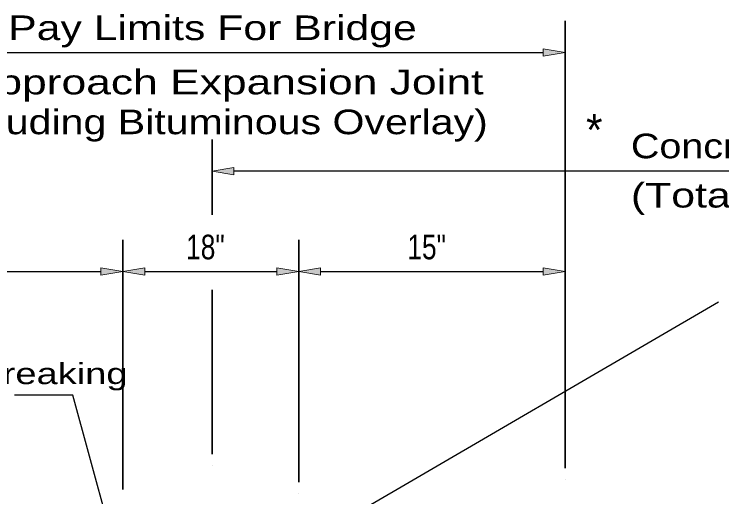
# Model space of a CAD drawing. Extents: x 36.4 to 71.7, y 0.5 to 22.5.
# Drawn here: x 46.897 to 50.926, y 10.127 to 12.873 of the extents above; entities that cross this region are included whole.
import ezdxf

# ---------------------------------------------------------------- set-up
doc = ezdxf.new("R2010")
doc.units = 0
doc.header["$LTSCALE"] = 0.056
for name, color, linetype, lineweight in [('1', 7, 'Continuous', 40), ('3', 7, 'Continuous', 13), ('6', 7, 'Continuous', 13)]:
    doc.layers.add(name, color=color, linetype=linetype, lineweight=lineweight)

msp = doc.modelspace()

# ---------------------------------------------------------------- hatches: boundary and pattern name
at = {"layer": '1'}
for points in [[(49.90942, 12.63425), (49.90942, 12.67592), (50.03442, 12.65508), (50.03442, 12.65508)], [(48.14858, 11.95783), (48.14858, 11.9995), (48.02358, 11.97867), (48.02358, 11.97867)], [(47.39025, 11.38717), (47.39025, 11.42883), (47.51525, 11.408), (47.51525, 11.408)], [(47.64025, 11.38717), (47.64025, 11.42883), (47.51525, 11.408), (47.51525, 11.408)], [(48.39192, 11.38717), (48.39192, 11.42883), (48.51692, 11.408), (48.51692, 11.408)], [(48.64192, 11.38717), (48.64192, 11.42883), (48.51692, 11.408), (48.51692, 11.408)], [(49.90942, 11.38717), (49.90942, 11.42883), (50.03442, 11.408), (50.03442, 11.408)]]:
    msp.add_hatch(color=256, dxfattribs=at).paths.add_polyline_path(points)

# ---------------------------------------------------------------- linework, layer by layer
at = {"layer": '1', "lineweight": 35}
for p, q in [((50.03442, 10.35225), (50.03442, 12.83508)), ((48.02358, 11.73058), (48.02358, 12.15867)), ((47.51525, 10.16858), (47.51525, 11.588)), ((48.51692, 10.21008), (48.51692, 11.588)), ((50.03442, 10.28975), (50.03442, 11.588)), ((48.02358, 10.36925), (48.02358, 11.30483))]:
    msp.add_line(p, q, dxfattribs=at)
at = {"layer": '1', "lineweight": 25}
for p, q in [((46.16342, 12.65508), (49.90942, 12.65508)), ((57.66217, 11.97867), (48.14858, 11.97867)), ((46.16342, 11.408), (47.39025, 11.408)), ((47.64025, 11.408), (48.39192, 11.408)), ((48.64192, 11.408), (49.90942, 11.408))]:
    msp.add_line(p, q, dxfattribs=at)
at = {"layer": '1', "lineweight": 13}
for p, q in [((47.51525, 10.16858), (47.51525, 11.588)), ((48.51692, 10.21008), (48.51692, 11.588))]:
    msp.add_line(p, q, dxfattribs=at)
for points in [[(49.90942, 12.63425), (49.90942, 12.67592), (50.03442, 12.65508), (50.03442, 12.65508)], [(48.14858, 11.95783), (48.14858, 11.9995), (48.02358, 11.97867), (48.02358, 11.97867)], [(47.39025, 11.38717), (47.39025, 11.42883), (47.51525, 11.408), (47.51525, 11.408)], [(47.64025, 11.38717), (47.64025, 11.42883), (47.51525, 11.408), (47.51525, 11.408)], [(48.39192, 11.38717), (48.39192, 11.42883), (48.51692, 11.408), (48.51692, 11.408)], [(48.64192, 11.38717), (48.64192, 11.42883), (48.51692, 11.408), (48.51692, 11.408)], [(49.90942, 11.38717), (49.90942, 11.42883), (50.03442, 11.408), (50.03442, 11.408)]]:
    msp.add_lwpolyline(points, close=True, dxfattribs=at)
at = {"layer": '3', "lineweight": 25}
msp.add_line((48.52608, 9.85067), (50.90675, 11.2355), dxfattribs=at)
msp.add_lwpolyline([(47.633, 9.234), (47.23175, 10.70433), (46.89858, 10.70433)], dxfattribs=at)
at = {"layer": '6'}
for p, q in [((50.03442, 12.65508), (50.0345, 12.65508)), ((48.02358, 11.97867), (48.02367, 11.97867)), ((47.51525, 11.408), (47.51533, 11.408)), ((48.51692, 11.408), (48.517, 11.408)), ((50.03442, 11.408), (50.0345, 11.408)), ((48.02358, 10.30675), (48.02367, 10.30675)), ((50.03442, 10.28975), (50.0345, 10.28975)), ((50.03442, 10.22725), (50.0345, 10.22725)), ((48.51692, 10.14758), (48.517, 10.14758)), ((48.51692, 10.14758), (48.517, 10.14758))]:
    msp.add_line(p, q, dxfattribs=at)

# ---------------------------------------------------------------- texts
at = {"layer": '1'}
for s, width, p in [('Pay Limits For Bridge', 1.3, (46.86308, 12.72508)), ('18"', 0.8, (47.87608, 11.478)), ('15"', 0.8, (49.13567, 11.478))]:
    msp.add_text(s, height=0.14, dxfattribs=dict(at, width=width)).set_placement(p)
at = {"layer": '3'}
for s, height, width, p in [('Approach Expansion Joint', 0.14, 1.35, (46.63275, 12.41633)), ('(Excluding Bituminous Overlay)', 0.14, 1.25, (46.32925, 12.18967)), ("Concrete Bridge Transition Pavement 285' Maximum", 0.14, 1.2, (50.40867, 12.05283)), ('(Total Length as Shown or Specified on the Plans)', 0.14, 1.3, (50.40867, 11.77258)), ('Bond Breaking', 0.12, 1.35, (46.12125, 10.76792))]:
    msp.add_text(s, height=height, dxfattribs=dict(at, width=width)).set_placement(p)
msp.add_text('*', height=0.18, dxfattribs=at).set_placement((50.15333, 12.12433))

doc.saveas('drawing.dxf')
